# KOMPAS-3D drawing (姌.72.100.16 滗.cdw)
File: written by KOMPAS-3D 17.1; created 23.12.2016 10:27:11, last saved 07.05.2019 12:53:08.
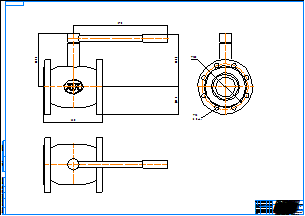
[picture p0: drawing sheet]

Sheet 1: A0, landscape

Title block, sheet 1: name: КШ.72.100.16 фф; material: Внимание! Данный продукт является объектом авторского права ООО «Торговый Дом АДЛ». / Запрещается изменение, копирование, распространение / (в том числе путем копирования на другие сайты и ресурсы в Интернете) / или любое иное использование информации и объектов без предварительного / согласия правообладателя (ООО «Торговый Дом АДЛ»).; sheets: 1; organisation: ООО "Торговый дом АДЛ"; sheet format: A0; stored path: C:\Users\tra\Desktop\2д чертежи\Шаровые краны БИВАЛ\КШ_Бивал_серия_72\KOMPAS_2D\КШ.72.100.16 фф.cdw

Views: Спереди 4, Проекционный вид 5, Проекционный вид 6
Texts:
  Klimkovich
  ADL
Dimensions and other numbers on the sheet: 230; 370; 205,1; 107,5; 207,6; 180; 18; 8 Отв.; 1:1; 1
